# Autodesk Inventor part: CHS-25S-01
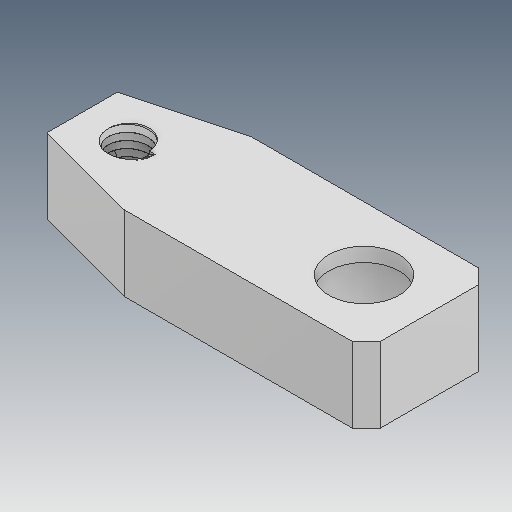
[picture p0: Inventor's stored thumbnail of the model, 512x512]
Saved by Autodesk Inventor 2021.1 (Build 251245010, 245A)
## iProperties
Created: 2021-05
Part Number: CHS-25S-01
Material: Ogólny
Document SubType Name: Modeling
Designer: user
Density: 1 g/cm^3
Appearance: Domyślna
Author: user
Revision Number: ÈÎºÎ
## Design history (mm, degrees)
feature "ÊäÈë1"
node "Bryła1"
